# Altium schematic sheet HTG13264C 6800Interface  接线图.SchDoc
size A4
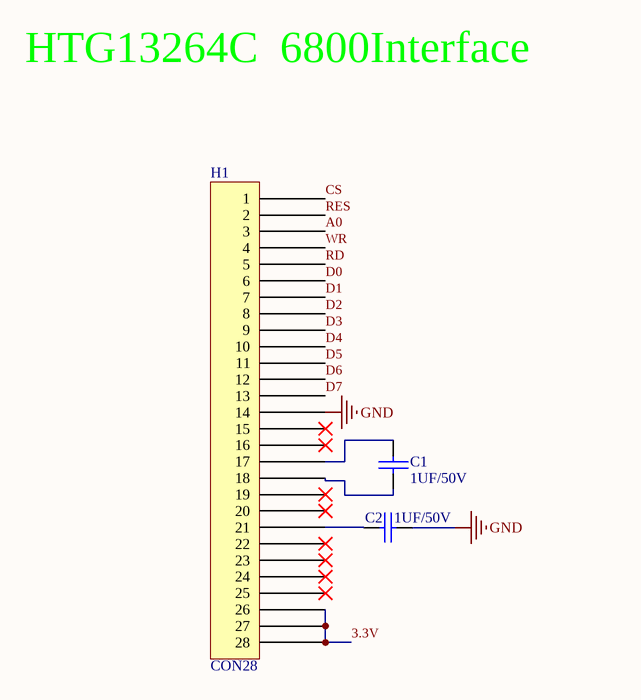
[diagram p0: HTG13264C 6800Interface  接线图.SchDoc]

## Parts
C1  1UF/50V  [0805CAP]
C2  1UF/50V  [0805CAP]
H1  CON28

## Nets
GND: C2.2 H1.14
3.3V: H1.26 H1.27 H1.28
A0: H1.3
CS: H1.1
D0: H1.6
D1: H1.7
D2: H1.8
D3: H1.9
D4: H1.10
D5: H1.11
D6: H1.12
D7: H1.13
RD: H1.5
RES: H1.2
WR: H1.4
NetC1_1: C1.1 H1.18
NetC1_2: C1.2 H1.17
NetC2_1: C2.1 H1.21

Not connected (* = marked no-connect by the designer): H1 15* 16* 19* 20* 22* 23* 24* 25*

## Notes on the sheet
- HTG13264C  6800Interface

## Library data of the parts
C1 C2 = CAP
